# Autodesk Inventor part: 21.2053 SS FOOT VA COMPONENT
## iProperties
Created: 2011-11
Part Number: 21.2053 SS FOOT VA COMPONENT
Document SubType Name: Modeling
Designer: Administrator
Density: 8.08 g/cm^3
Material: Stainless Steel
Mass: 1.9495 g
Surface Area: 4.2223 cm^2
Volume: 0.241274 cm^3
Author: Administrator
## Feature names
1. Base1
2. Extrusion1
